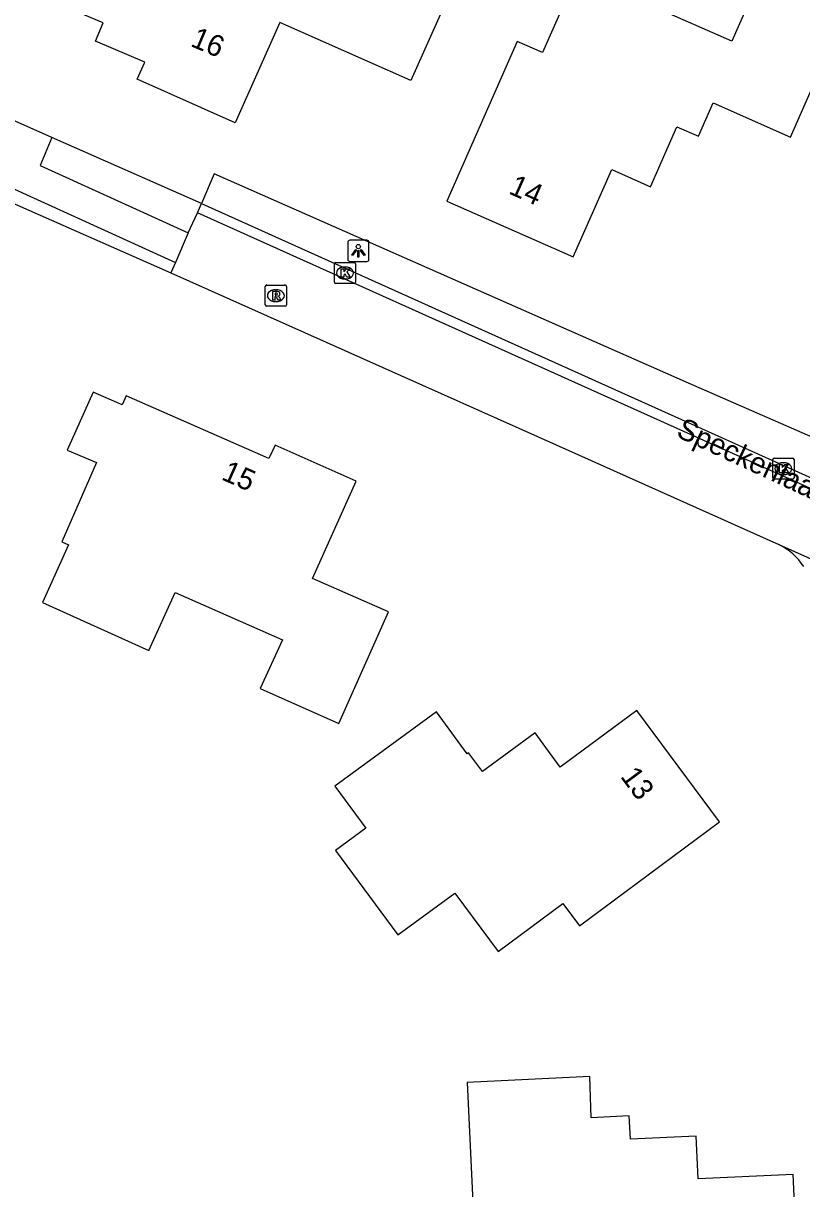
# Model space of a CAD drawing. Extents: x 162157 to 163165, y 378998 to 380775.
# Drawn here: x 162225.6 to 162262.2, y 380237.1 to 380291.9 of the extents above; entities that cross this region are included whole.
import ezdxf

# ---------------------------------------------------------------- set-up
doc = ezdxf.new("R2010")
doc.units = 0
for name, color, linetype in [('IMGEO_Groenvoorziening', 7, 'Continuous'), ('IMGEO_Kolk', 7, 'Continuous'), ('IMGEO_Lichtpunt', 7, 'Continuous'), ('IMGEO_Openbare_ruimte_label', 7, 'Continuous'), ('IMGEO_Pand', 7, 'Continuous'), ('IMGEO_Pand_nummerreeks', 7, 'Continuous'), ('IMGEO_Parkeervlak_open', 7, 'Continuous'), ('IMGEO_Rijbaan_lokaal_open', 7, 'Continuous'), ('IMGEO_Rioolput', 7, 'Continuous'), ('IMGEO_Voetpad_open', 7, 'Continuous')]:
    doc.layers.add(name, color=color, linetype=linetype)

msp = doc.modelspace()

# ---------------------------------------------------------------- linework, layer by layer
at = {"layer": 'IMGEO_Groenvoorziening'}
for points in [[(162216.316, 380287.317), (162232.517, 380280.173)], [(162233.962, 380283.439), (162226.912, 380286.545)]]:
    msp.add_lwpolyline(points, dxfattribs=at)
at = {"layer": 'IMGEO_Kolk'}
for p, q in [((162240.217, 380279.742), (162240.217, 380280.594)), ((162240.292, 380280.668), (162241.144, 380280.668)), ((162240.705, 380280.448), (162240.73, 380280.448)), ((162241.218, 380280.594), (162241.218, 380279.742)), ((162240.728, 380279.888), (162240.703, 380279.888)), ((162241.144, 380279.668), (162240.292, 380279.668)), ((162260.934, 380271.459), (162261.786, 380271.459)), ((162260.859, 380270.533), (162260.859, 380271.385)), ((162261.347, 380271.239), (162261.372, 380271.239)), ((162261.86, 380271.385), (162261.86, 380270.533)), ((162261.786, 380270.459), (162260.934, 380270.459)), ((162261.37, 380270.679), (162261.345, 380270.679))]:
    msp.add_line(p, q, dxfattribs=at)
for points in [[(162240.217, 380279.742), (162240.217, 380280.594)], [(162240.292, 380280.668), (162241.144, 380280.668)], [(162240.538, 380280.368), (162240.661, 380280.368), (162240.661, 380280.217), (162240.791, 380280.368), (162240.955, 380280.368), (162240.809, 380280.217), (162240.962, 380279.968), (162240.81, 380279.968), (162240.725, 380280.132), (162240.661, 380280.065), (162240.661, 380279.968), (162240.538, 380279.968), (162240.538, 380280.368)], [(162241.218, 380280.594), (162241.218, 380279.742)], [(162241.144, 380279.668), (162240.292, 380279.668)], [(162260.934, 380271.459), (162261.786, 380271.459)], [(162260.859, 380270.533), (162260.859, 380271.385)], [(162261.18, 380271.159), (162261.303, 380271.159), (162261.303, 380271.008), (162261.433, 380271.159), (162261.597, 380271.159), (162261.451, 380271.008), (162261.604, 380270.759), (162261.452, 380270.759), (162261.367, 380270.923), (162261.303, 380270.856), (162261.303, 380270.759), (162261.18, 380270.759), (162261.18, 380271.159)], [(162261.86, 380271.385), (162261.86, 380270.533)], [(162261.786, 380270.459), (162260.934, 380270.459)]]:
    msp.add_lwpolyline(points, dxfattribs=at)
for centre, start, end in [((162240.294, 380280.592), 91.552, 178.448), ((162240.294, 380280.592), 91.552, 178.448), ((162241.142, 380280.592), 1.552, 88.448), ((162241.142, 380280.592), 1.552, 88.448), ((162240.294, 380279.744), 181.552, 268.448), ((162240.294, 380279.744), 181.552, 268.448), ((162241.142, 380279.744), 271.552, 358.448), ((162241.142, 380279.744), 271.552, 358.448), ((162260.936, 380271.383), 91.552, 178.448), ((162260.936, 380271.383), 91.552, 178.448), ((162261.784, 380271.383), 1.552, 88.448), ((162261.784, 380271.383), 1.552, 88.448), ((162260.936, 380270.535), 181.552, 268.448), ((162260.936, 380270.535), 181.552, 268.448), ((162261.784, 380270.535), 271.552, 358.448), ((162261.784, 380270.535), 271.552, 358.448)]:
    msp.add_arc(centre, 0.0765, start, end, dxfattribs=at)
for centre, major_axis, ratio, start_param, end_param in [((162240.704, 380280.168), (-0.387, 0.002), 0.722429, 4.712389, 7.853982), ((162240.729, 380280.168), (-0.39, 0.002), 0.717154, 1.570796, 4.712389), ((162261.346, 380270.959), (-0.387, 0.002), 0.722429, 4.712389, 7.853982), ((162261.371, 380270.959), (-0.39, 0.002), 0.717154, 1.570796, 4.712389)]:
    msp.add_ellipse(centre, major_axis=major_axis, ratio=ratio, start_param=start_param, end_param=end_param, dxfattribs=at)
at = {"layer": 'IMGEO_Lichtpunt'}
for p, q in [((162240.85, 380281.612), (162240.85, 380280.805)), ((162240.85, 380281.612), (162240.85, 380280.805)), ((162241.752, 380281.707), (162240.944, 380281.707)), ((162241.752, 380281.707), (162240.944, 380281.707)), ((162241.846, 380280.805), (162241.846, 380281.612)), ((162241.846, 380280.805), (162241.846, 380281.612)), ((162240.944, 380280.711), (162241.752, 380280.711)), ((162240.944, 380280.711), (162241.752, 380280.711))]:
    msp.add_line(p, q, dxfattribs=at)
for points in [[(162241.224, 380281.276), (162241.263, 380281.248), (162241.075, 380280.986), (162241.037, 380281.013), (162241.224, 380281.276)], [(162241.326, 380281.228), (162241.373, 380281.228), (162241.373, 380280.906), (162241.326, 380280.906), (162241.326, 380281.228)], [(162241.436, 380281.248), (162241.474, 380281.275), (162241.661, 380281.013), (162241.622, 380280.985), (162241.436, 380281.248)]]:
    msp.add_lwpolyline(points, dxfattribs=at)
msp.add_circle((162241.349, 380281.41), 0.0994, dxfattribs=at)
for centre, start, end in [((162240.944, 380281.612), 90, 180), ((162240.944, 380281.612), 90, 180), ((162241.752, 380281.612), 0, 90), ((162241.752, 380281.612), 0, 90), ((162240.944, 380280.805), 180, 270), ((162240.944, 380280.805), 180, 270), ((162241.752, 380280.805), 270, 0), ((162241.752, 380280.805), 270, 360)]:
    msp.add_arc(centre, 0.0946, start, end, dxfattribs=at)
at = {"layer": 'IMGEO_Pand'}
for points in [[(162243.811, 380289.227), (162237.655, 380291.963), (162235.552, 380287.241), (162230.939, 380289.296), (162231.293, 380290.09), (162228.972, 380291.073), (162229.338, 380291.939), (162226.667, 380293.069), (162230.004, 380300.952), (162235.465, 380298.64), (162235.122, 380297.83), (162236, 380297.458), (162235.555, 380296.406), (162238.732, 380295.061), (162241.211, 380300.918), (162247.796, 380298.131), (162243.811, 380289.227)], [(162251.661, 380294.287), (162250.012, 380290.544), (162248.822, 380291.068), (162245.508, 380283.546), (162251.463, 380280.922), (162253.275, 380285.035), (162255.105, 380284.229), (162256.348, 380287.05), (162257.362, 380286.604), (162258.05, 380288.169), (162261.692, 380286.565), (162264.107, 380292.045), (162260.131, 380293.797), (162258.935, 380291.082), (162251.661, 380294.287)], [(162239.188, 380265.787), (162241.241, 380270.367), (162237.43, 380272.057), (162237.138, 380271.429), (162230.422, 380274.393), (162230.226, 380273.963), (162228.856, 380274.562), (162227.639, 380271.823), (162229.017, 380271.245), (162227.383, 380267.51), (162227.7, 380267.378), (162226.474, 380264.663), (162231.487, 380262.4), (162232.722, 380265.134), (162237.778, 380262.895), (162236.721, 380260.612), (162240.431, 380258.963), (162242.767, 380264.217), (162239.188, 380265.787)], [(162240.243, 380256.02), (162241.695, 380254.034), (162240.267, 380252.989), (162243.204, 380249.01), (162245.891, 380250.98), (162247.924, 380248.23), (162250.979, 380250.488), (162251.756, 380249.439), (162258.358, 380254.33), (162254.46, 380259.569), (162250.843, 380256.907), (162249.665, 380258.519), (162247.192, 380256.697), (162246.53, 380257.58), (162246.47, 380257.535), (162245.02, 380259.516), (162240.243, 380256.02)], [(162246.476, 380242.067), (162246.783, 380235.425), (162249.78, 380235.563), (162249.946, 380231.967), (162253.842, 380232.147), (162253.902, 380230.849), (162262.124, 380231.229), (162261.822, 380237.739), (162257.348, 380237.528), (162257.251, 380239.541), (162254.159, 380239.392), (162254.103, 380240.493), (162252.314, 380240.403), (162252.244, 380242.346), (162246.476, 380242.067)]]:
    msp.add_lwpolyline(points, dxfattribs=at)
at = {"layer": 'IMGEO_Parkeervlak_open'}
msp.add_lwpolyline([(162313.48, 380239.458), (162309.062, 380242.979), (162284.653, 380262.244), (162264.941, 380271.336), (162264.973, 380271.455), (162256.885, 380274.976), (162234.564, 380284.836), (162233.962, 380283.439)], dxfattribs=at)
at = {"layer": 'IMGEO_Rijbaan_lokaal_open'}
for points in [[(162233.328, 380282.059), (162233.766, 380282.994)], [(162233.766, 380282.994), (162233.962, 380283.439)], [(162311.336, 380239.172), (162311.046, 380238.809), (162307.42, 380241.672), (162283.16, 380260.799), (162233.766, 380282.994)], [(162233.962, 380283.439), (162283.411, 380261.197), (162307.687, 380242.035), (162311.336, 380239.172)], [(162233.328, 380282.059), (162232.737, 380280.664)], [(162232.737, 380280.664), (162232.517, 380280.173)], [(162232.517, 380280.173), (162250.669, 380272.072), (162261.152, 380267.394)], [(162261.152, 380267.394), (162265.283, 380265.541)]]:
    msp.add_lwpolyline(points, dxfattribs=at)
msp.add_arc((162259.702, 380264.588), 3.158, 33.9672, 62.6623, dxfattribs=at)
at = {"layer": 'IMGEO_Rioolput'}
for p, q in [((162236.962, 380278.676), (162236.962, 380279.528)), ((162237.037, 380279.602), (162237.889, 380279.602)), ((162237.45, 380279.382), (162237.475, 380279.382)), ((162237.963, 380279.528), (162237.963, 380278.676)), ((162237.889, 380278.602), (162237.037, 380278.602)), ((162237.473, 380278.822), (162237.448, 380278.822))]:
    msp.add_line(p, q, dxfattribs=at)
for points in [[(162236.962, 380278.676), (162236.962, 380279.528)], [(162237.037, 380279.602), (162237.889, 380279.602)], [(162237.551, 380279.3), (162237.299, 380279.302), (162237.299, 380278.902)], [(162237.477, 380279.221), (162237.423, 380279.221), (162237.423, 380279.14)], [(162237.423, 380279.14), (162237.475, 380279.14)], [(162237.963, 380279.528), (162237.963, 380278.676)], [(162237.889, 380278.602), (162237.037, 380278.602)], [(162237.299, 380278.902), (162237.423, 380278.902), (162237.423, 380279.064), (162237.434, 380279.064)], [(162237.481, 380279.035), (162237.552, 380278.902), (162237.692, 380278.902), (162237.627, 380279.028)]]:
    msp.add_lwpolyline(points, dxfattribs=at)
for centre, radius, start, end in [((162237.039, 380279.526), 0.0765, 91.552, 178.448), ((162237.039, 380279.526), 0.0765, 91.552, 178.448), ((162237.459, 380279.329), 0.19, 274.7715, 282.9687), ((162237.483, 380279.125), 0.0964, 77.0061, 93.1865), ((162237.497, 380279.182), 0.0378, 276.6634, 79.6772), ((162237.55, 380279.19), 0.109, 350.3612, 89.416), ((162237.548, 380279.19), 0.112, 277.5842, 350.9817), ((162237.887, 380279.526), 0.0765, 1.552, 88.448), ((162237.887, 380279.526), 0.0765, 1.552, 88.448), ((162237.039, 380278.678), 0.0765, 181.552, 268.448), ((162237.039, 380278.678), 0.0765, 181.552, 268.448), ((162237.433, 380279.011), 0.0533, 26.0293, 88.6989), ((162237.532, 380278.975), 0.108, 29.5134, 73.7905), ((162237.887, 380278.678), 0.0765, 271.552, 358.448), ((162237.887, 380278.678), 0.0765, 271.552, 358.448)]:
    msp.add_arc(centre, radius, start, end, dxfattribs=at)
for centre, major_axis, ratio, start_param, end_param in [((162237.449, 380279.102), (-0.387, 0.002), 0.722429, 4.712389, 7.853982), ((162237.474, 380279.102), (-0.39, 0.002), 0.717154, 1.570796, 4.712389)]:
    msp.add_ellipse(centre, major_axis=major_axis, ratio=ratio, start_param=start_param, end_param=end_param, dxfattribs=at)
at = {"layer": 'IMGEO_Voetpad_open'}
for points in [[(162216.517, 380288.038), (162232.737, 380280.664)], [(162226.912, 380286.545), (162225.195, 380287.308)], [(162226.912, 380286.545), (162226.365, 380285.232), (162233.328, 380282.059)]]:
    msp.add_lwpolyline(points, dxfattribs=at)

# ---------------------------------------------------------------- texts
at = {"layer": 'IMGEO_Openbare_ruimte_label'}
msp.add_text('Speckenlaan', height=1, rotation=335.1008, dxfattribs=at).set_placement((162256.265, 380272.489))
at = {"layer": 'IMGEO_Pand_nummerreeks'}
for s, rotation, p in [('16', 337.0621, (162233.396, 380290.864)), ('14', 336.0217, (162248.376, 380283.925)), ('15', 336.0847, (162234.852, 380270.466)), ('13', 306.6519, (162253.653, 380256.465))]:
    msp.add_text(s, height=1, rotation=rotation, dxfattribs=at).set_placement(p)

doc.saveas('drawing.dxf')
